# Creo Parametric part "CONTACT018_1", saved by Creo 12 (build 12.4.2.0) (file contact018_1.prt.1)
Units: Custom; MM, KILOGRAM, SECS

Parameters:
  PTC_WM_ITERATION = "0"
  PTC_WM_VERSION = "-.0"
  PTC_WM_LIFECYCLE_STATE = "In Work"
  PTC_WM_LIFECYCLE = "MO_CADDocument"
  PTC_WM_CREATED_BY = "Maximilian Roepper (Z0017RMS: MO)"
  PTC_WM_CREATED_ON = "18-Sep-26 11:36:42 AM"
  PTC_WM_MODIFIED_BY = "Maximilian Roepper (Z0017RMS: MO)"
  PTC_WM_MODIFIED_ON = "18-Sep-26 11:36:46 AM"
  PDMLINKNUMBER = "PDM000071454770"
  PTC_WM_NAME = "contact018_1.prt"
  PTC_WM_NUMBER = "PDM000071454770"

Other parameters: WEIGHT, WEIGHT_FACTOR, WEIGHT_ADD, _MASS_TEMP, _DIFF_TEMP, MC_ERRORS, SUPPLIER

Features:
  1. coordinate system
  2. datum plane "PRT_YZ"
  3. datum plane "PRT_XY"
  4. datum plane "PRT_XZ"
  5. coordinate system
  6. datum axis
  7. datum axis
  8. datum axis
  9. coordinate system
  10. imported feature

Other named items: PRT, SIEMENS_MO, DRW_VIEW_ORG, PRT_X, PRT_Y, PRT_Z, CS0, ROUGH_GROB

Layers: 00_STD_CSYS-KSYS, 01_STD_PLANES-EBENEN, 02_STD_AXES-ACHSEN, 03_STD_CSYS-KSYS, 24_IMPORT_FEAT-IMPORT_KE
